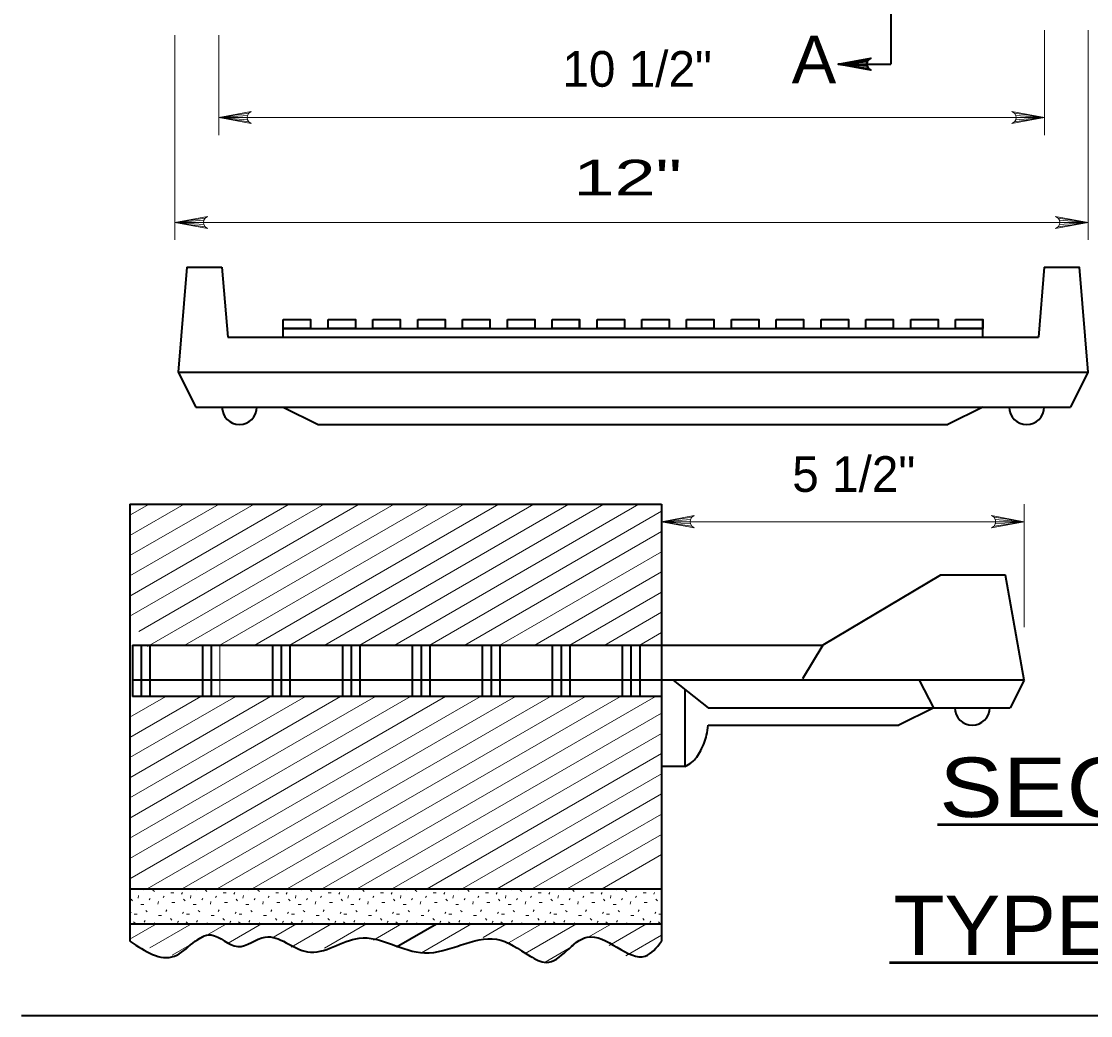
# Model space of a CAD drawing. Extents: x 15 to 140, y -57 to 117.
# Drawn here: x 15.07 to 45.63, y -2.09 to 26.34 of the extents above; entities that cross this region are included whole.
import ezdxf
from ezdxf.enums import TextEntityAlignment as Align

# ---------------------------------------------------------------- set-up
doc = ezdxf.new("R2010")
doc.units = 0
doc.header["$LTSCALE"] = 0.41
for name, color, linetype, lineweight in [('1', 7, 'Continuous', 35), ('10', 7, 'Continuous', 13), ('12', 7, 'Continuous', 53), ('13', 7, 'Continuous', 53), ('6', 7, 'Continuous', 13)]:
    doc.layers.add(name, color=color, linetype=linetype, lineweight=lineweight)

msp = doc.modelspace()

# ---------------------------------------------------------------- linework, layer by layer
at = {"layer": '1'}
for p, q in [((19.8062, 19.3097), (19.5562, 16.3097)), ((19.8062, 19.3097), (20.8062, 19.3097)), ((20.8062, 19.3097), (20.9729, 17.3097)), ((44.3062, 19.3097), (44.1396, 17.3097)), ((31.0253, 17.5597), (31.0253, 17.8097)), ((42.5562, 17.3097), (42.5562, 17.8097)), ((22.5562, 17.5597), (42.5562, 17.5597)), ((20.9729, 17.3097), (44.1396, 17.3097)), ((19.5562, 16.3097), (45.5562, 16.3097)), ((19.5562, 16.3097), (20.0562, 15.3097)), ((45.5562, 16.3097), (45.0562, 15.3097)), ((20.0562, 15.3097), (45.0562, 15.3097)), ((22.5562, 15.3097), (23.5562, 14.8097)), ((42.5562, 15.3097), (41.5562, 14.8097)), ((23.5562, 14.8097), (41.5562, 14.8097)), ((18.1768, 12.5315), (33.3717, 12.5315)), ((18.1768, 12.5315), (18.1768, 0.0315)), ((33.3717, 12.5315), (33.3717, 0.0315)), ((41.3461, 10.5023), (37.9829, 8.5023)), ((43.2039, 10.5023), (41.3461, 10.5023)), ((43.7329, 7.5023), (43.2039, 10.5023)), ((18.2467, 8.5023), (37.9829, 8.5023)), ((18.2467, 8.5023), (18.2467, 7.0315)), ((18.4967, 8.5023), (18.4967, 7.0315)), ((18.7467, 8.5023), (18.7467, 7.0315)), ((20.2467, 8.5023), (20.2467, 7.0315)), ((20.4967, 8.5023), (20.4967, 7.0315)), ((22.2467, 8.5023), (22.2467, 7.0315)), ((22.4967, 8.5023), (22.4967, 7.0315)), ((22.7467, 8.5023), (22.7467, 7.0315)), ((24.2467, 8.5023), (24.2467, 7.0315)), ((24.4967, 8.5023), (24.4967, 7.0315)), ((24.7467, 8.5023), (24.7467, 7.0315)), ((26.2467, 8.5023), (26.2467, 7.0315)), ((26.4967, 8.5023), (26.4967, 7.0315)), ((26.7467, 8.5023), (26.7467, 7.0315)), ((28.2467, 8.5023), (28.2467, 7.0315)), ((28.4967, 8.5023), (28.4967, 7.0315)), ((28.7467, 8.5023), (28.7467, 7.0315)), ((30.2467, 8.5023), (30.2467, 7.0315)), ((30.4967, 8.5023), (30.4967, 7.0315)), ((30.7467, 8.5023), (30.7467, 7.0315)), ((32.2467, 8.5023), (32.2467, 7.0315)), ((32.4967, 8.5023), (32.4967, 7.0315)), ((32.7467, 8.5023), (32.7467, 7.0315)), ((37.9829, 8.5023), (37.3966, 7.5347)), ((43.7329, 7.5023), (18.2467, 7.5023)), ((33.3717, 7.5023), (33.3717, 5.0315)), ((33.7052, 7.4984), (34.7051, 6.713)), ((41.1544, 6.713), (40.753, 7.4764)), ((43.7329, 7.5023), (43.3383, 6.713)), ((33.3717, 7.0315), (18.2467, 7.0315)), ((34.0384, 7.2366), (34.0384, 5.0315)), ((34.7051, 6.713), (43.3383, 6.713)), ((41.1544, 6.713), (40.1544, 6.213)), ((34.7051, 6.213), (40.1544, 6.213)), ((34.0384, 5.0315), (33.3717, 5.0315)), ((18.1768, 1.5315), (33.3717, 1.5315)), ((18.1768, 0.5315), (33.3717, 0.5315)), ((25.7983, -0.1273), (26.9394, 0.5315)), ((15.0728, -2.0932), (140.4342, -2.0932))]:
    msp.add_line(p, q, dxfattribs=at)
for points in [[(44.3062, 19.3097), (45.3062, 19.3097), (45.5562, 16.3097)], [(22.5562, 17.3097), (22.5562, 17.5597), (22.5562, 17.8097)]]:
    msp.add_lwpolyline(points, dxfattribs=at)
for points in [[(22.5562, 17.8097), (23.3375, 17.8097), (23.3375, 17.5597), (22.5562, 17.5597)], [(23.8375, 17.8097), (24.6188, 17.8097), (24.6188, 17.5597), (23.8375, 17.5597)], [(25.1188, 17.8097), (25.9001, 17.8097), (25.9001, 17.5597), (25.1188, 17.5597)], [(26.4001, 17.8097), (27.1814, 17.8097), (27.1814, 17.5597), (26.4001, 17.5597)], [(27.6814, 17.8097), (28.4627, 17.8097), (28.4627, 17.5597), (27.6814, 17.5597)], [(28.9627, 17.8097), (29.744, 17.8097), (29.744, 17.5597), (28.9627, 17.5597)], [(30.244, 17.8097), (31.0253, 17.8097), (31.0253, 17.5597), (30.244, 17.5597)], [(31.5253, 17.8097), (32.3066, 17.8097), (32.3066, 17.5597), (31.5253, 17.5597)], [(32.8066, 17.8097), (33.5879, 17.8097), (33.5879, 17.5597), (32.8066, 17.5597)], [(34.0879, 17.8097), (34.8692, 17.8097), (34.8692, 17.5597), (34.0879, 17.5597)], [(35.3692, 17.8097), (36.1505, 17.8097), (36.1505, 17.5597), (35.3692, 17.5597)], [(36.6505, 17.8097), (37.4318, 17.8097), (37.4318, 17.5597), (36.6505, 17.5597)], [(37.9318, 17.8097), (38.7131, 17.8097), (38.7131, 17.5597), (37.9318, 17.5597)], [(39.2131, 17.8097), (39.9944, 17.8097), (39.9944, 17.5597), (39.2131, 17.5597)], [(40.4944, 17.8097), (41.2757, 17.8097), (41.2757, 17.5597), (40.4944, 17.5597)], [(41.775, 17.8097), (42.5562, 17.8097), (42.5562, 17.5597), (41.775, 17.5597)]]:
    msp.add_lwpolyline(points, close=True, dxfattribs=at)
for centre in [(21.3063, 15.3097), (43.8063, 15.3097), (42.2497, 6.7112)]:
    msp.add_arc(centre, 0.5, 180, 0, dxfattribs=at)
for points in [[(34.0384, 5.0315), (34.2305, 5.1479), (34.4891, 5.4872), (34.6588, 5.9233), (34.7051, 6.213)], [(18.1768, 0.0315), (19.4447, -0.3905), (20.501, 0.2135), (21.2555, -0.1187), (22.0402, 0.1531), (23.2475, -0.2697), (24.7263, 0.1229), (26.5975, -0.2999), (28.6498, 0.0927), (29.6156, -0.3905), (30.0683, -0.5717), (31.2454, 0.1531), (32.9054, -0.3905), (33.3717, 0.0315)]]:
    msp.add_spline(points, degree=3, dxfattribs=at)
at = {"layer": '10', "lineweight": 35}
for p in [(39.9208, 30.1165), (38.4208, 25.1165)]:
    msp.add_line(p, (39.9208, 25.1165), dxfattribs=at)
at = {"layer": '10'}
for p, q in [((44.3156, 26.0891), (44.3156, 23.0891)), ((45.5656, 26.0891), (45.5656, 20.0891)), ((19.463, 25.9484), (19.463, 20.0891)), ((20.713, 25.9484), (20.713, 23.0891)), ((20.713, 23.5891), (44.3156, 23.5891)), ((19.463, 20.5891), (45.5656, 20.5891)), ((43.7329, 9.0181), (43.7329, 12.5315)), ((33.3717, 12.0315), (43.7329, 12.0315))]:
    msp.add_line(p, q, dxfattribs=at)
at = {"layer": '10', "lineweight": 35}
msp.add_lwpolyline([(38.4208, 25.1165), (39.3529, 25.2912), (39.281, 25.2415), (39.244, 25.179), (39.2333, 25.1165), (39.244, 25.054), (39.281, 24.9915), (39.3529, 24.9417), (38.4208, 25.1165), (39.281, 24.9915), (39.244, 25.054), (38.4208, 25.1165), (39.2333, 25.1165), (39.244, 25.179), (38.4208, 25.1165), (39.281, 25.2415)], dxfattribs=at)
at = {"layer": '10'}
for points in [[(20.713, 23.5891), (21.6451, 23.7638), (21.5733, 23.7141), (21.5362, 23.6516), (21.5255, 23.5891), (21.5362, 23.5266), (21.5733, 23.4641), (21.6451, 23.4143), (20.713, 23.5891), (21.5733, 23.4641), (21.5362, 23.5266), (20.713, 23.5891), (21.5255, 23.5891), (21.5362, 23.6516), (20.713, 23.5891), (21.5733, 23.7141)], [(44.3156, 23.5891), (43.3835, 23.4143), (43.4553, 23.4641), (43.4924, 23.5266), (43.5031, 23.5891), (43.4924, 23.6516), (43.4553, 23.7141), (43.3835, 23.7638), (44.3156, 23.5891), (43.4553, 23.7141), (43.4924, 23.6516), (44.3156, 23.5891), (43.5031, 23.5891), (43.4924, 23.5266), (44.3156, 23.5891), (43.4553, 23.4641)], [(19.463, 20.5891), (20.3951, 20.7638), (20.3233, 20.7141), (20.2862, 20.6516), (20.2755, 20.5891), (20.2862, 20.5266), (20.3233, 20.4641), (20.3951, 20.4143), (19.463, 20.5891), (20.3233, 20.4641), (20.2862, 20.5266), (19.463, 20.5891), (20.2755, 20.5891), (20.2862, 20.6516), (19.463, 20.5891), (20.3233, 20.7141)], [(45.5656, 20.5891), (44.6335, 20.4143), (44.7053, 20.4641), (44.7424, 20.5266), (44.7531, 20.5891), (44.7424, 20.6516), (44.7053, 20.7141), (44.6335, 20.7638), (45.5656, 20.5891), (44.7053, 20.7141), (44.7424, 20.6516), (45.5656, 20.5891), (44.7531, 20.5891), (44.7424, 20.5266), (45.5656, 20.5891), (44.7053, 20.4641)], [(33.3717, 12.0315), (34.3038, 12.2062), (34.232, 12.1565), (34.195, 12.094), (34.1842, 12.0315), (34.195, 11.969), (34.232, 11.9065), (34.3038, 11.8567), (33.3717, 12.0315), (34.232, 11.9065), (34.195, 11.969), (33.3717, 12.0315), (34.1842, 12.0315), (34.195, 12.094), (33.3717, 12.0315), (34.232, 12.1565)], [(43.7329, 12.0315), (42.8008, 11.8567), (42.8726, 11.9065), (42.9097, 11.969), (42.9204, 12.0315), (42.9097, 12.094), (42.8726, 12.1565), (42.8008, 12.2062), (43.7329, 12.0315), (42.8726, 12.1565), (42.9097, 12.094), (43.7329, 12.0315), (42.9204, 12.0315), (42.9097, 11.969), (43.7329, 12.0315), (42.8726, 11.9065)]]:
    msp.add_lwpolyline(points, dxfattribs=at)
at = {"layer": '12'}
for p, q in [((41.2528, 3.3742), (58.7891, 3.3742)), ((39.8852, -0.5764), (48.7353, -0.5764))]:
    msp.add_line(p, q, dxfattribs=at)
at = {"layer": '6'}
for p, q in [((18.1768, 9.3288), (23.724, 12.5315)), ((18.1768, 9.9062), (22.724, 12.5315)), ((18.1768, 10.4835), (21.724, 12.5315)), ((18.1768, 11.0609), (20.724, 12.5315)), ((18.1768, 11.6382), (19.724, 12.5315)), ((18.1768, 12.2156), (18.724, 12.5315)), ((18.4268, 8.8958), (24.724, 12.5315)), ((18.6768, 8.4628), (25.724, 12.5315)), ((19.7452, 8.5023), (26.724, 12.5315)), ((20.7452, 8.5023), (27.724, 12.5315)), ((21.7453, 8.5023), (28.724, 12.5315)), ((22.7452, 8.5023), (29.724, 12.5315)), ((23.7453, 8.5023), (30.724, 12.5315)), ((24.7452, 8.5023), (31.724, 12.5315)), ((25.7453, 8.5023), (32.724, 12.5315)), ((26.7452, 8.5023), (33.3717, 12.3281)), ((27.7453, 8.5023), (33.3717, 11.7508)), ((28.7452, 8.5023), (33.3717, 11.1734)), ((29.7453, 8.5023), (33.3717, 10.596)), ((30.7453, 8.5023), (33.3717, 10.0187)), ((31.7452, 8.5023), (33.3717, 9.4414)), ((32.7452, 8.5023), (33.3717, 8.864)), ((20.7467, 8.5023), (20.7467, 7.0315)), ((18.1768, 6.4421), (19.1977, 7.0315)), ((18.1768, 5.8647), (20.1977, 7.0315)), ((18.1768, 5.2874), (21.1977, 7.0315)), ((18.1768, 4.71), (22.1977, 7.0315)), ((18.1768, 4.1326), (23.1977, 7.0315)), ((18.1768, 3.5553), (24.1977, 7.0315)), ((18.1768, 2.978), (25.1977, 7.0315)), ((18.1768, 2.4006), (26.1977, 7.0315)), ((18.1768, 1.8233), (27.1977, 7.0315)), ((18.6714, 1.5315), (28.1977, 7.0315)), ((19.6714, 1.5315), (29.1977, 7.0315)), ((20.6714, 1.5315), (30.1977, 7.0315)), ((21.6714, 1.5315), (31.1977, 7.0315)), ((22.6714, 1.5315), (32.1977, 7.0315)), ((23.6714, 1.5315), (33.1977, 7.0315)), ((24.6714, 1.5315), (33.3717, 6.5546)), ((25.6714, 1.5315), (33.3717, 5.9772)), ((26.6714, 1.5315), (33.3717, 5.3999)), ((27.6714, 1.5315), (33.3717, 4.8225)), ((28.6714, 1.5315), (33.3717, 4.2452)), ((29.6714, 1.5315), (33.3717, 3.6679)), ((30.6714, 1.5315), (33.3717, 3.0905)), ((31.6714, 1.5315), (33.3717, 2.5131)), ((18.5505, 1.5315), (18.5783, 1.5037)), ((20.0505, 1.5315), (20.0783, 1.5037)), ((21.5505, 1.5315), (21.5783, 1.5037)), ((23.0505, 1.5315), (23.0783, 1.5037)), ((24.5505, 1.5315), (24.5783, 1.5037)), ((26.0505, 1.5315), (26.0783, 1.5037)), ((27.5505, 1.5315), (27.5783, 1.5037)), ((29.0505, 1.5315), (29.0783, 1.5037)), ((30.5505, 1.5315), (30.5783, 1.5037)), ((32.0505, 1.5315), (32.0783, 1.5037)), ((18.2085, 1.2352), (18.2509, 1.1929)), ((18.4204, 1.3412), (18.4063, 1.2635)), ((18.7267, 1.2141), (18.7549, 1.2565)), ((18.8326, 1.4966), (18.875, 1.4543)), ((19.1222, 1.2847), (19.1505, 1.3271)), ((19.3412, 1.4189), (19.4259, 1.4189)), ((19.5884, 1.5178), (19.6732, 1.5178)), ((19.6449, 1.3836), (19.6732, 1.426)), ((19.7085, 1.2352), (19.7509, 1.1929)), ((19.9204, 1.3412), (19.9063, 1.2635)), ((20.2267, 1.2141), (20.2549, 1.2565)), ((20.3326, 1.4966), (20.375, 1.4543)), ((20.6222, 1.2847), (20.6505, 1.3271)), ((20.8412, 1.4189), (20.9259, 1.4189)), ((21.0884, 1.5178), (21.1732, 1.5178)), ((21.1449, 1.3836), (21.1732, 1.426)), ((21.2085, 1.2352), (21.2509, 1.1929)), ((21.4204, 1.3412), (21.4063, 1.2635)), ((21.7267, 1.2141), (21.7549, 1.2565)), ((21.8326, 1.4966), (21.875, 1.4543)), ((22.1222, 1.2847), (22.1505, 1.3271)), ((22.3412, 1.4189), (22.4259, 1.4189)), ((22.5884, 1.5178), (22.6732, 1.5178)), ((22.6449, 1.3836), (22.6732, 1.426)), ((22.7085, 1.2352), (22.7509, 1.1929)), ((22.9204, 1.3412), (22.9063, 1.2635)), ((23.2267, 1.2141), (23.2549, 1.2565)), ((23.3326, 1.4966), (23.375, 1.4543)), ((23.6222, 1.2847), (23.6505, 1.3271)), ((23.8412, 1.4189), (23.9259, 1.4189)), ((24.0884, 1.5178), (24.1732, 1.5178)), ((24.1449, 1.3836), (24.1732, 1.426)), ((24.2085, 1.2352), (24.2509, 1.1929)), ((24.4204, 1.3412), (24.4063, 1.2635)), ((24.7267, 1.2141), (24.7549, 1.2565)), ((24.8326, 1.4966), (24.875, 1.4543)), ((25.1222, 1.2847), (25.1505, 1.3271)), ((25.3412, 1.4189), (25.4259, 1.4189)), ((25.5884, 1.5178), (25.6732, 1.5178)), ((25.6449, 1.3836), (25.6732, 1.426)), ((25.7085, 1.2352), (25.7509, 1.1929)), ((25.9204, 1.3412), (25.9063, 1.2635)), ((26.2267, 1.2141), (26.2549, 1.2565)), ((26.3326, 1.4966), (26.375, 1.4543)), ((26.6222, 1.2847), (26.6505, 1.3271)), ((26.8412, 1.4189), (26.9259, 1.4189)), ((27.0884, 1.5178), (27.1732, 1.5178)), ((27.1449, 1.3836), (27.1732, 1.426)), ((27.2085, 1.2352), (27.2509, 1.1929)), ((27.4204, 1.3412), (27.4063, 1.2635)), ((27.7267, 1.2141), (27.7549, 1.2565)), ((27.8326, 1.4966), (27.875, 1.4543)), ((28.1222, 1.2847), (28.1505, 1.3271)), ((28.3412, 1.4189), (28.4259, 1.4189)), ((28.5884, 1.5178), (28.6732, 1.5178)), ((28.6449, 1.3836), (28.6732, 1.426)), ((28.7085, 1.2352), (28.7509, 1.1929)), ((28.9204, 1.3412), (28.9063, 1.2635)), ((29.2267, 1.2141), (29.2549, 1.2565)), ((29.3326, 1.4966), (29.375, 1.4543)), ((29.6222, 1.2847), (29.6505, 1.3271)), ((29.8412, 1.4189), (29.9259, 1.4189)), ((30.0884, 1.5178), (30.1732, 1.5178)), ((30.1449, 1.3836), (30.1732, 1.426)), ((30.2085, 1.2352), (30.2509, 1.1929)), ((30.4204, 1.3412), (30.4063, 1.2635)), ((30.7267, 1.2141), (30.7549, 1.2565)), ((30.8326, 1.4966), (30.875, 1.4543)), ((31.1222, 1.2847), (31.1505, 1.3271)), ((31.3412, 1.4189), (31.4259, 1.4189)), ((31.5884, 1.5178), (31.6732, 1.5178)), ((31.6449, 1.3836), (31.6732, 1.426)), ((31.7085, 1.2352), (31.7509, 1.1929)), ((31.9204, 1.3412), (31.9063, 1.2635)), ((32.2267, 1.2141), (32.2549, 1.2565)), ((32.3326, 1.4966), (32.375, 1.4543)), ((32.6222, 1.2847), (32.6505, 1.3271)), ((32.8412, 1.4189), (32.9259, 1.4189)), ((33.0884, 1.5178), (33.1732, 1.5178)), ((33.1449, 1.3836), (33.1732, 1.426)), ((33.2085, 1.2352), (33.2509, 1.1929)), ((18.4865, 1.0869), (18.5712, 1.0869)), ((18.988, 1.1717), (18.9739, 1.094)), ((19.1999, 0.8866), (19.2282, 0.9291)), ((19.3765, 1.1434), (19.4612, 1.1434)), ((19.9865, 1.0869), (20.0712, 1.0869)), ((20.488, 1.1717), (20.4739, 1.094)), ((20.6999, 0.8866), (20.7282, 0.9291)), ((20.8765, 1.1434), (20.9612, 1.1434)), ((21.4865, 1.0869), (21.5712, 1.0869)), ((21.988, 1.1717), (21.9739, 1.094)), ((22.1999, 0.8866), (22.2282, 0.9291)), ((22.3765, 1.1434), (22.4612, 1.1434)), ((22.9865, 1.0869), (23.0712, 1.0869)), ((23.488, 1.1717), (23.4739, 1.094)), ((23.6999, 0.8866), (23.7282, 0.9291)), ((23.8765, 1.1434), (23.9612, 1.1434)), ((24.4865, 1.0869), (24.5712, 1.0869)), ((24.988, 1.1717), (24.9739, 1.094)), ((25.1999, 0.8866), (25.2282, 0.9291)), ((25.3765, 1.1434), (25.4612, 1.1434)), ((25.9865, 1.0869), (26.0712, 1.0869)), ((26.488, 1.1717), (26.4739, 1.094)), ((26.6999, 0.8866), (26.7282, 0.9291)), ((26.8765, 1.1434), (26.9612, 1.1434)), ((27.4865, 1.0869), (27.5712, 1.0869)), ((27.988, 1.1717), (27.9739, 1.094)), ((28.1999, 0.8866), (28.2282, 0.9291)), ((28.3765, 1.1434), (28.4612, 1.1434)), ((28.9865, 1.0869), (29.0712, 1.0869)), ((29.488, 1.1717), (29.4739, 1.094)), ((29.6999, 0.8866), (29.7282, 0.9291)), ((29.8765, 1.1434), (29.9612, 1.1434)), ((30.4865, 1.0869), (30.5712, 1.0869)), ((30.988, 1.1717), (30.9739, 1.094)), ((31.1999, 0.8866), (31.2282, 0.9291)), ((31.3765, 1.1434), (31.4612, 1.1434)), ((31.9865, 1.0869), (32.0712, 1.0869)), ((32.488, 1.1717), (32.4739, 1.094)), ((32.6999, 0.8866), (32.7282, 0.9291)), ((32.8765, 1.1434), (32.9612, 1.1434)), ((18.1802, 0.8231), (18.2085, 0.8655)), ((18.2932, 0.8089), (18.378, 0.8089)), ((18.5783, 0.5829), (18.6065, 0.6253)), ((18.6278, 0.9149), (18.6702, 0.8725)), ((18.9951, 0.7666), (19.0799, 0.7666)), ((19.3341, 0.6817), (19.3765, 0.6394)), ((19.6802, 0.8231), (19.7085, 0.8655)), ((19.7932, 0.8089), (19.878, 0.8089)), ((20.0783, 0.5829), (20.1065, 0.6253)), ((20.1278, 0.9149), (20.1702, 0.8725)), ((20.4951, 0.7666), (20.5799, 0.7666)), ((20.8341, 0.6817), (20.8765, 0.6394)), ((21.1802, 0.8231), (21.2085, 0.8655)), ((21.2932, 0.8089), (21.378, 0.8089)), ((21.5783, 0.5829), (21.6065, 0.6253)), ((21.6278, 0.9149), (21.6702, 0.8725)), ((21.9951, 0.7666), (22.0799, 0.7666)), ((22.3341, 0.6817), (22.3765, 0.6394)), ((22.6802, 0.8231), (22.7085, 0.8655)), ((22.7932, 0.8089), (22.878, 0.8089)), ((23.0783, 0.5829), (23.1065, 0.6253)), ((23.1278, 0.9149), (23.1702, 0.8725)), ((23.4951, 0.7666), (23.5799, 0.7666)), ((23.8341, 0.6817), (23.8765, 0.6394)), ((24.1802, 0.8231), (24.2085, 0.8655)), ((24.2932, 0.8089), (24.378, 0.8089)), ((24.5783, 0.5829), (24.6065, 0.6253)), ((24.6278, 0.9149), (24.6702, 0.8725)), ((24.9951, 0.7666), (25.0799, 0.7666)), ((25.3341, 0.6817), (25.3765, 0.6394)), ((25.6802, 0.8231), (25.7085, 0.8655)), ((25.7932, 0.8089), (25.878, 0.8089)), ((26.0783, 0.5829), (26.1065, 0.6253)), ((26.1278, 0.9149), (26.1702, 0.8725)), ((26.4951, 0.7666), (26.5799, 0.7666)), ((26.8341, 0.6817), (26.8765, 0.6394)), ((27.1802, 0.8231), (27.2085, 0.8655)), ((27.2932, 0.8089), (27.378, 0.8089)), ((27.5783, 0.5829), (27.6065, 0.6253)), ((27.6278, 0.9149), (27.6702, 0.8725)), ((27.9951, 0.7666), (28.0799, 0.7666)), ((28.3341, 0.6817), (28.3765, 0.6394)), ((28.6802, 0.8231), (28.7085, 0.8655)), ((28.7932, 0.8089), (28.878, 0.8089)), ((29.0783, 0.5829), (29.1065, 0.6253)), ((29.1278, 0.9149), (29.1702, 0.8725)), ((29.4951, 0.7666), (29.5799, 0.7666)), ((29.8341, 0.6817), (29.8765, 0.6394)), ((30.1802, 0.8231), (30.2085, 0.8655)), ((30.2932, 0.8089), (30.378, 0.8089)), ((30.5783, 0.5829), (30.6065, 0.6253)), ((30.6278, 0.9149), (30.6702, 0.8725)), ((30.9951, 0.7666), (31.0799, 0.7666)), ((31.3341, 0.6817), (31.3765, 0.6394)), ((31.6802, 0.8231), (31.7085, 0.8655)), ((31.7932, 0.8089), (31.878, 0.8089)), ((32.0783, 0.5829), (32.1065, 0.6253)), ((32.1278, 0.9149), (32.1702, 0.8725)), ((32.4951, 0.7666), (32.5799, 0.7666)), ((32.8341, 0.6817), (32.8765, 0.6394)), ((33.1802, 0.8231), (33.2085, 0.8655)), ((33.2932, 0.8089), (33.3717, 0.8089)), ((18.1768, 0.0912), (18.9394, 0.5315)), ((18.2791, 0.5899), (18.3215, 0.5476)), ((18.7455, -0.1578), (19.9394, 0.5315)), ((18.8689, 0.5315), (18.8891, 0.5617)), ((19.3799, -0.3689), (20.9394, 0.5315)), ((19.5319, 0.5687), (19.5602, 0.6112)), ((19.7791, 0.5899), (19.8215, 0.5476)), ((20.3689, 0.5315), (20.3891, 0.5617)), ((20.9807, -0.022), (21.9394, 0.5315)), ((21.0319, 0.5687), (21.0602, 0.6112)), ((21.2791, 0.5899), (21.3215, 0.5476)), ((21.8689, 0.5315), (21.8891, 0.5617)), ((22.2271, 0.1202), (22.9394, 0.5315)), ((22.5319, 0.5687), (22.5602, 0.6112)), ((22.7791, 0.5899), (22.8215, 0.5476)), ((22.7827, -0.1363), (23.9394, 0.5315)), ((23.3689, 0.5315), (23.3891, 0.5617)), ((23.7397, -0.1612), (24.9394, 0.5315)), ((24.0319, 0.5687), (24.0602, 0.6112)), ((24.2791, 0.5899), (24.3215, 0.5476)), ((24.8689, 0.5315), (24.8891, 0.5617)), ((25.1361, 0.0677), (25.9394, 0.5315)), ((25.5319, 0.5687), (25.5602, 0.6112)), ((25.7791, 0.5899), (25.8215, 0.5476)), ((26.3689, 0.5315), (26.3891, 0.5617)), ((26.5103, -0.2936), (27.9394, 0.5315)), ((27.0319, 0.5687), (27.0602, 0.6112)), ((27.2791, 0.5899), (27.3215, 0.5476)), ((27.8689, 0.5315), (27.8891, 0.5617)), ((28.2676, 0.1436), (28.9394, 0.5315)), ((28.5319, 0.5687), (28.5602, 0.6112)), ((28.7791, 0.5899), (28.8215, 0.5476)), ((28.951, -0.0392), (29.9394, 0.5315)), ((29.3689, 0.5315), (29.3891, 0.5617)), ((29.4676, -0.3183), (30.9394, 0.5315)), ((30.0319, 0.5687), (30.0602, 0.6112)), ((30.2791, 0.5899), (30.3215, 0.5476)), ((30.8689, 0.5315), (30.8891, 0.5617)), ((31.2903, 0.1567), (31.9394, 0.5315)), ((31.5319, 0.5687), (31.5602, 0.6112)), ((31.7791, 0.5899), (31.8215, 0.5476)), ((31.8729, -0.0842), (32.9394, 0.5315)), ((32.3689, 0.5315), (32.3891, 0.5617)), ((33.0319, 0.5687), (33.0602, 0.6112)), ((33.2791, 0.5899), (33.3215, 0.5476)), ((32.3521, -0.3849), (33.3717, 0.2037)), ((30.0432, -0.5633), (30.847, -0.0992))]:
    msp.add_line(p, q, dxfattribs=at)

# ---------------------------------------------------------------- texts
at = {"layer": '12'}
for s, height, width, p in [('A', 1.36, 1.05, (37.7267, 24.5684)), ('SECTION A-A', 1.7, 1.2, (50.021, 3.5867)), ('TYPE C', 1.7, 1.05, (44.3102, -0.3639))]:
    msp.add_text(s, height=height, dxfattribs=dict(at, width=width)).set_placement(p, align=Align.CENTER)
at = {"layer": '13'}
for s, p in [('10 1/2"', (32.6717, 24.4696)), ('5 1/2"', (38.8645, 12.8848))]:
    msp.add_text(s, height=1.02, dxfattribs=at).set_placement(p, align=Align.CENTER)
at = {"layer": '13', "width": 1.55}
msp.add_text('12"', height=1.02, dxfattribs=at).set_placement((32.3992, 21.3617), align=Align.CENTER)

doc.saveas('drawing.dxf')
